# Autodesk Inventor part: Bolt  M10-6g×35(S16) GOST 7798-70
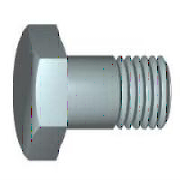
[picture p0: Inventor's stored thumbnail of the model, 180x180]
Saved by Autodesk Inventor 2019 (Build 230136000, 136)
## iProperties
Created: 2018-01
Part Number: Bolt  M10-6g×35(S16) GOST 7798-70
Material: Steel, Mild
Description: Hexagon bolts, product grade B
Document SubType Name: Modeling
Standard: GOST 7798-70
Designer: m.vorobev
Standards Organization: GOST
Language: en-US
Size Designation: M10-6g×35(S16)
Categories: <MemberInstance><Categories><Category DisplayName="Fasteners" InternalName="e4da775c-781d-43d5-af7c-5136215cf5a6" Mnemonic="FSTN"><Category DisplayName="Bolts"
Mass: 4.46121 g
Surface Area: 4.48844 cm^2
Volume: 0.567584 cm^3
Density: 7.85 g/cm^3
Appearance: Semi-Polished
IsCustomPart: 0
Title: Bolt
Author: m.vorobev
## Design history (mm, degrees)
sketch "Sketch1"
  geometry: L1 (0, 0)-(7.6, 0); L2 (12, -2.54)-(12, -6.4); L3 (12, -6.4)-(5, -6.4); L4 (5, -6.4)-(5, -41.4); L5 (5, -41.4)-(0, -41.4); L6 (0, -41.4)-(0, 0); L7 (7.6, 0)-(12, -2.54)
  constraints: 14 end point, 4 parallel, 1 horizontal, 1 perpendicular
  dimensions: "d0" = 24 diameter of L2 L6 (= 1.5 x S_); "d1" = 10 diameter of L4 L6 (= d1_); "d2" = 6.4 distance between parallel lines of L1 L3 (= k); "d3" = 35 distance between parallel lines of L3 L5 (= L); "d20" = 30 deg angle of L1 L7; "d21" = 15.2 diameter of L1.end L6 (= 0.95 x S_)
revolve "Revolution1" sketch "Sketch1" stored, may be unused: angle "d4" = 90 deg
thread "Thread1" dims "d12" = 26 (= b), "d13" = 0
chamfer "Chamfer1" distance "d14" = 0.83333 (= 0.0833333 x d); stored, may be unused: second distance "d15" = 2, angle "d16" = 45 deg
body "Solid1"
sketch "Sketch2"
  geometry: L1 (0, -9.238)-(-8, -4.619); L2 (-8, -4.619)-(-8, 4.619); L3 (-8, 4.619)-(0, 9.238); L4 (0, 9.238)-(8, 4.619); L5 (8, 4.619)-(8, -4.619); L6 (8, -4.619)-(0, -9.238); C1 r 12 at (0, 0) reference; 2 further points
  constraints: 12 end point, 1 coincident, 1 vertical alignment, 13 other
  dimensions: "d22" = 16 distance between parallel lines of L5 L2 (= S_)
extrude "Extrusion1" cut sketch "Sketch2" distance "d23" = 6.4 (= k); taper "d24" = 0 deg
other parameters: "d1_" = 10 [user parameter; used in 1 equation term], "S_" = 16 [user parameter; used in 3 equation terms], "k" = 6.4 [user parameter; used in 2 equation terms], "e" = 17.6 [user parameter], "L" = 35 [user parameter; used in 1 equation term], "b" = 26 [user parameter; used in 1 equation term], "Grip_Length" = 9 [user parameter], "d17" = 0, "d18" = 0, "d19" = 0
